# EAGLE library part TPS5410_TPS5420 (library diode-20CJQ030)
Ti's TPS5410 and TPS5420 1A or 2A, WIDE INPUT RANGE, STEP-DOWN SWIFT CONVERTER Description: As a member of the SWIFT family of DC/DC regulators, the TPS5410/TPS5420 is a high-output-current PWM converter that integrates a low resistance high side N-channel MOSFET. Included on the substrate with the listed features is a high performance voltage error amplifier that provides tight voltage regulation accuracy under transient conditions; an undervoltage-lockout circuit to prevent start-up until the input voltage reaches 5.5 V; an internally set slow-start circuit to prevent start-up until the input volatge feed-forward circuit to improve the transient response. Using the ENA pin, shutdown supply current is reduced to 18 mA typically. Other features include an active high enable, overcurrent protection and thermal shutdown. To reduce design complexity and external component count, the TPS5410 feedback loop is internally compensated. The TPS5410/TPS5420 device is available in an easy to use 8-pin SOIC package. TI provides evaluation modules and software tools to aid in quickly achieving high-performance power supply designs to meet aggressive equipment development cycles. Features: Wide Input Voltage Range: 5.5 V to 36 V Up to 1-A Continuous (1.2-A Peak) Output Current High Efficiency up to 95% Enabled by 110-mW Integrated MOSFET Switch Wide Output Voltage Range: Adjustable Down to 1.22 V with 1.5% Initial Accuracy Internal Compensation Minimizes External Parts Count Fixed 500-kHz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
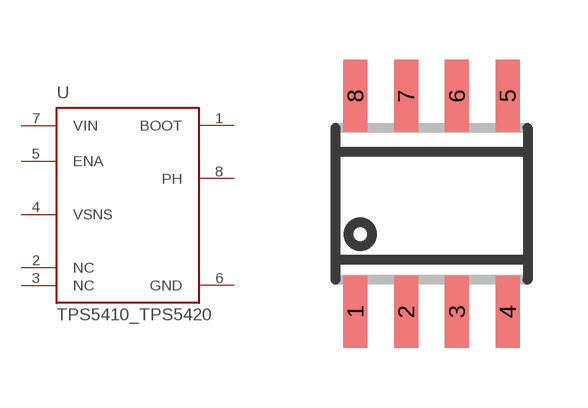
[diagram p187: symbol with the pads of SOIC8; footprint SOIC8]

Designator prefix U

## TPS5410_TPS5420D  [SOIC8]
1  BOOT  pas
2  NC  nc
3  NC  nc
4  VSNS  pas
5  ENA  in
6  GND  pwr
7  VIN  pwr
8  PH  pas

## Footprint SOIC8 (pad centres in mm)
Small Outline IC
smd 0.6 x 1.8: 1 -1.905,-2.7; 2 -0.635,-2.7; 3 0.635,-2.7; 4 1.905,-2.7; 5 1.905,2.7; 6 0.635,2.7; 7 -0.635,2.7; 8 -1.905,2.7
